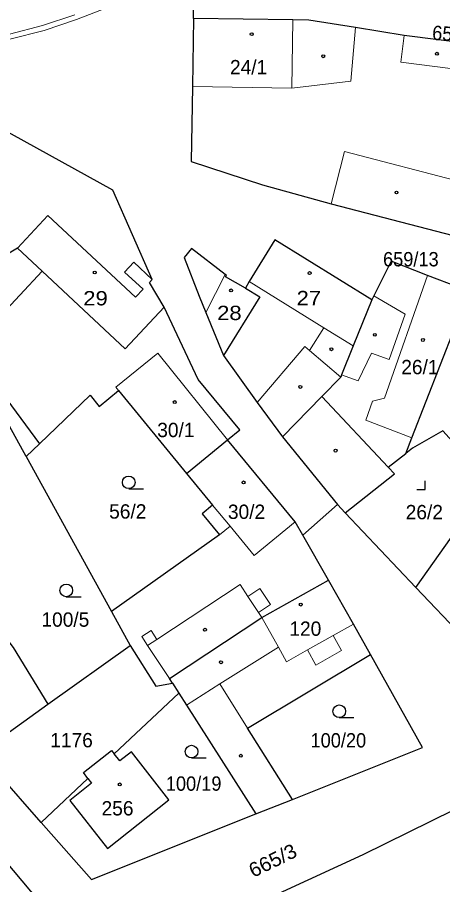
# Model space of a CAD drawing. Extents: x -758887 to -754328, y -1031688 to -1029144.
# Drawn here: x -756312.6 to -756262.1, y -1030550.3 to -1030447.4 of the extents above; entities that cross this region are included whole.
import ezdxf
from ezdxf.enums import TextEntityAlignment as Align

# ---------------------------------------------------------------- set-up
doc = ezdxf.new("R2010")
doc.units = 0
doc.header["$LTSCALE"] = 0.68
for name, color, linetype, lineweight in [('1', 7, 'Continuous', 25), ('13', 7, 'Continuous', 13), ('3', 7, 'Continuous', 25), ('4', 7, 'Continuous', 13), ('5', 7, 'Continuous', 25)]:
    doc.layers.add(name, color=color, linetype=linetype, lineweight=lineweight)
doc.layers.add('2', color=7, linetype='Continuous')

msp = doc.modelspace()

# ---------------------------------------------------------------- linework, layer by layer
at = {"layer": '1'}
for p, q in [((-756291.68, -1030447.55), (-756291.6, -1030443.2)), ((-756292.48, -1030501.5), (-756287.62, -1030497.5)), ((-756281.1, -1030497.15), (-756274.56, -1030505.16)), ((-756265.25, -1030515.03), (-756256.49, -1030502.6)), ((-756278.68, -1030508.83), (-756274.56, -1030505.16)), ((-756275.62, -1030514.13), (-756278.68, -1030508.83)), ((-756265.25, -1030515.03), (-756252.53, -1030528.46)), ((-756308.95, -1030528.87), (-756299.17, -1030521.88)), ((-756293.42, -1030527.54), (-756301.08, -1030534.74)), ((-756317.02, -1030534.63), (-756308.95, -1030528.87)), ((-756309.74, -1030542.89), (-756317.02, -1030534.63)), ((-756304.2, -1030537.67), (-756309.74, -1030542.89)), ((-756284.28, -1030541.87), (-756279.91, -1030540.14))]:
    msp.add_line(p, q, dxfattribs=at)
for points in [[(-756291.68, -1030447.55), (-756291.8, -1030455.61), (-756291.93, -1030464.52)], [(-756252.57, -1030451.52), (-756258.83, -1030450.57), (-756266.65, -1030449.57), (-756272.45, -1030448.6), (-756277.96, -1030447.75), (-756279.88, -1030447.72), (-756291.68, -1030447.55)], [(-756295.16, -1030481.76), (-756296.9, -1030478.86), (-756296.56, -1030478.49), (-756301.26, -1030467.91), (-756316.33, -1030459.62)], [(-756291.93, -1030464.52), (-756283.46, -1030467.28), (-756275.34, -1030469.53), (-756260.84, -1030473.29)], [(-756309.65, -1030477.51), (-756312.58, -1030474.78), (-756314.65, -1030475.99), (-756321.14, -1030471.61)], [(-756270.49, -1030480.92), (-756282.03, -1030473.78), (-756285.04, -1030478.74), (-756285.51, -1030479.51)], [(-756285.51, -1030479.51), (-756287.86, -1030478.19), (-756287.76, -1030478.01), (-756287.92, -1030477.89), (-756291.9, -1030474.82), (-756292.79, -1030475.9), (-756290.99, -1030480.46), (-756290.22, -1030482.42), (-756288.1, -1030487.49)], [(-756263.88, -1030478.04), (-756268.2, -1030476.33), (-756270.25, -1030480.45), (-756270.49, -1030480.92)], [(-756309.65, -1030477.51), (-756314.96, -1030483.22), (-756313.79, -1030484.31), (-756317.3, -1030488.07), (-756309.97, -1030497.97)], [(-756309.65, -1030477.51), (-756299.77, -1030486.71), (-756295.16, -1030481.76)], [(-756258.94, -1030479.89), (-756260.13, -1030479.44), (-756263.88, -1030478.04)], [(-756285.51, -1030479.51), (-756283.81, -1030480.56), (-756288.1, -1030487.49)], [(-756266.46, -1030499.12), (-756265.73, -1030497.26), (-756258.94, -1030479.89)], [(-756270.49, -1030480.92), (-756272.69, -1030486.38), (-756274.08, -1030489.82), (-756274.19, -1030490.09), (-756276.43, -1030492.38), (-756281.1, -1030497.15)], [(-756287.62, -1030497.5), (-756286.17, -1030496.31), (-756291.12, -1030490.34), (-756295.16, -1030481.76)], [(-756288.1, -1030487.49), (-756284.12, -1030493.1), (-756281.1, -1030497.15)], [(-756309.97, -1030497.97), (-756303.94, -1030492.23), (-756302.86, -1030493.54), (-756300.58, -1030491.67), (-756292.48, -1030501.5)], [(-756311.54, -1030499.47), (-756313.51, -1030495.89), (-756330.09, -1030509.29)], [(-756256.49, -1030502.6), (-756262.05, -1030496.44), (-756265.67, -1030498.5), (-756266.46, -1030499.12)], [(-756278.68, -1030508.83), (-756279.61, -1030507.23), (-756287.62, -1030497.5)], [(-756309.97, -1030497.97), (-756311.54, -1030499.47), (-756301.4, -1030517.85)], [(-756273.64, -1030506.17), (-756267.79, -1030501.56), (-756268.54, -1030500.76), (-756266.46, -1030499.12)], [(-756292.48, -1030501.5), (-756289.4, -1030505.25), (-756290.63, -1030506.27), (-756288.57, -1030508.78), (-756301.4, -1030517.85), (-756299.17, -1030521.88)], [(-756274.56, -1030505.16), (-756273.64, -1030506.17), (-756265.25, -1030515.03)], [(-756294.17, -1030526.36), (-756294.52, -1030525.81), (-756283.55, -1030518.59), (-756275.62, -1030514.13)], [(-756270.66, -1030522.96), (-756272.68, -1030519.36), (-756275.62, -1030514.13)], [(-756314.73, -1030516.53), (-756313.61, -1030518.09), (-756315.11, -1030519.53), (-756313.06, -1030522.12), (-756308.95, -1030528.87)], [(-756299.17, -1030521.88), (-756296.14, -1030526.71), (-756294.17, -1030526.36), (-756293.42, -1030527.54)], [(-756279.91, -1030540.14), (-756285.25, -1030531.68), (-756270.66, -1030522.96)], [(-756279.91, -1030540.14), (-756264.47, -1030533.99), (-756270.66, -1030522.96)], [(-756293.42, -1030527.54), (-756292.51, -1030528.97), (-756284.28, -1030541.87)], [(-756304.2, -1030537.67), (-756303.78, -1030538.21), (-756306.36, -1030540.26), (-756301.89, -1030545.97), (-756294.58, -1030540.2), (-756299.01, -1030534.52), (-756300.41, -1030535.56), (-756301.08, -1030534.74)], [(-756304.2, -1030537.67), (-756304.74, -1030536.97), (-756301.39, -1030534.35), (-756301.08, -1030534.74)], [(-756276.81, -1030615.63), (-756276.9, -1030606.22), (-756295.51, -1030569.46), (-756318.87, -1030541.69)], [(-756238.06, -1030581.25), (-756260.8, -1030541.42), (-756271.57, -1030546.71), (-756294.15, -1030557.1), (-756273.96, -1030597.77)], [(-756309.74, -1030542.89), (-756303.79, -1030549.64), (-756284.28, -1030541.87)]]:
    msp.add_lwpolyline(points, dxfattribs=at)
at = {"layer": '13'}
for points in [[(-756317.15, -1030444.76), (-756315.55, -1030449.81), (-756313.48, -1030450), (-756309.41, -1030448.97), (-756305.55, -1030447.66), (-756295.4, -1030443.7)], [(-756305.75, -1030447.1), (-756309.59, -1030448.39), (-756313.52, -1030449.4), (-756315.09, -1030449.25), (-756316.59, -1030444.54)]]:
    msp.add_lwpolyline(points, dxfattribs=at)
at = {"layer": '3'}
for p, q in [((-756299.363, -1030503.3), (-756297.613, -1030503.3)), ((-756306.773, -1030516.12), (-756305.023, -1030516.12)), ((-756274.363, -1030530.44), (-756272.613, -1030530.44)), ((-756291.903, -1030535.23), (-756290.153, -1030535.23))]:
    msp.add_line(p, q, dxfattribs=at)
msp.add_lwpolyline([(-756265.161, -1030503.38), (-756264.16, -1030503.38), (-756264.16, -1030502.38)], dxfattribs=at)
for centre in [(-756299.3629, -1030502.5498), (-756306.7729, -1030515.3698), (-756274.3629, -1030529.6898), (-756291.9029, -1030534.4798)]:
    msp.add_circle(centre, 0.75, dxfattribs=at)
at = {"layer": '4'}
for p, q in [((-756279.88, -1030447.72), (-756280, -1030455.79)), ((-756267.06, -1030452.74), (-756266.65, -1030449.57)), ((-756280, -1030455.79), (-756291.8, -1030455.61)), ((-756273.73, -1030463.33), (-756275.34, -1030469.53)), ((-756259.7, -1030466.97), (-756273.73, -1030463.33)), ((-756308.97, -1030470.9), (-756312.58, -1030474.78)), ((-756298.54, -1030480.61), (-756308.97, -1030470.9)), ((-756298.76, -1030476.44), (-756299.85, -1030477.62)), ((-756296.56, -1030478.49), (-756298.76, -1030476.44)), ((-756299.85, -1030477.62), (-756297.65, -1030479.66)), ((-756287.92, -1030477.89), (-756290.22, -1030482.42)), ((-756285.04, -1030478.74), (-756276.2, -1030484.21)), ((-756269, -1030492.56), (-756263.88, -1030478.04)), ((-756297.65, -1030479.66), (-756298.54, -1030480.61)), ((-756270.25, -1030480.45), (-756266.54, -1030482.62)), ((-756266.54, -1030482.62), (-756268.45, -1030487.99)), ((-756277.88, -1030486.93), (-756276.2, -1030484.21)), ((-756272.69, -1030486.38), (-756276.2, -1030484.21)), ((-756278.45, -1030486.43), (-756284.12, -1030493.1)), ((-756300.9, -1030491.28), (-756300.58, -1030491.67)), ((-756276.43, -1030492.38), (-756268.54, -1030500.76)), ((-756271.2, -1030495.18), (-756270.4, -1030492.92)), ((-756270.4, -1030492.92), (-756269, -1030492.56)), ((-756271.2, -1030495.18), (-756265.73, -1030497.26)), ((-756289.4, -1030505.25), (-756287.33, -1030507.76)), ((-756288.57, -1030508.78), (-756287.33, -1030507.76)), ((-756284.47, -1030511.23), (-756287.33, -1030507.76)), ((-756284.47, -1030511.23), (-756279.61, -1030507.23)), ((-756286.13, -1030514.67), (-756296.02, -1030521.17)), ((-756285.2, -1030516.09), (-756286.13, -1030514.67)), ((-756283.78, -1030515.15), (-756285.2, -1030516.09)), ((-756282.54, -1030517.03), (-756283.78, -1030515.15)), ((-756285.2, -1030516.09), (-756283.96, -1030517.97)), ((-756283.96, -1030517.97), (-756282.54, -1030517.03)), ((-756283.96, -1030517.97), (-756283.55, -1030518.59)), ((-756281.59, -1030522.08), (-756283.55, -1030518.59)), ((-756297.8, -1030520.84), (-756296.71, -1030520.13)), ((-756296.71, -1030520.13), (-756296.02, -1030521.17)), ((-756275.09, -1030520.72), (-756272.68, -1030519.36)), ((-756297.8, -1030520.84), (-756297.11, -1030521.89)), ((-756296.02, -1030521.17), (-756297.11, -1030521.89)), ((-756278.15, -1030522.43), (-756275.09, -1030520.72)), ((-756275.09, -1030520.72), (-756274.09, -1030522.5)), ((-756297.11, -1030521.89), (-756294.52, -1030525.81)), ((-756280.61, -1030523.82), (-756281.59, -1030522.08)), ((-756280.61, -1030523.82), (-756278.15, -1030522.43)), ((-756277.14, -1030524.22), (-756278.15, -1030522.43)), ((-756274.09, -1030522.5), (-756277.14, -1030524.22)), ((-756285.25, -1030531.68), (-756288.53, -1030526.46))]:
    msp.add_line(p, q, dxfattribs=at)
for points in [[(-756272.45, -1030448.6), (-756272.99, -1030454.99), (-756280, -1030455.79)], [(-756267.06, -1030452.74), (-756259.31, -1030453.73), (-756259.97, -1030458.08)], [(-756300.9, -1030491.28), (-756295.91, -1030487.25), (-756287.62, -1030497.5)], [(-756278.45, -1030486.43), (-756277.88, -1030486.93), (-756274.19, -1030490.09)], [(-756274.08, -1030489.82), (-756272.1, -1030490.51), (-756270.52, -1030487.25), (-756268.45, -1030487.99)], [(-756292.51, -1030528.97), (-756288.53, -1030526.46), (-756281.59, -1030522.08)]]:
    msp.add_lwpolyline(points, dxfattribs=at)
at = {"layer": '5'}
for centre in [(-756284.7568, -1030449.4092), (-756276.2668, -1030452.0192), (-756262.7668, -1030451.7292), (-756267.5668, -1030468.1792), (-756303.3868, -1030477.6692), (-756277.8768, -1030477.7392), (-756287.2068, -1030479.7892), (-756270.1368, -1030485.0592), (-756264.4268, -1030485.6692), (-756275.2868, -1030486.7692), (-756278.9868, -1030491.2292), (-756293.8868, -1030493.0392), (-756274.7968, -1030498.7892), (-756285.7268, -1030502.5592), (-756278.9368, -1030517.0492), (-756290.3068, -1030520.0292), (-756288.4068, -1030523.8792), (-756286.0468, -1030534.9692), (-756300.4268, -1030538.3692)]:
    msp.add_circle(centre, 0.175, dxfattribs=at)

# ---------------------------------------------------------------- texts
at = {"layer": '2'}
for s, rotation, width, p in [('659/10', 356, 0.95, (-756260.0788, -1030450.3004)), ('665/3', 26, 1.05, (-756281.8891, -1030548.1522))]:
    msp.add_text(s, height=1.7, rotation=rotation, dxfattribs=dict(at, width=width)).set_placement(p, align=Align.CENTER)
for s, p in [('24/1', (-756285.12, -1030454.17)), ('26/1', (-756264.79, -1030489.73)), ('30/1', (-756293.76, -1030497.19)), ('56/2', (-756299.47, -1030506.85)), ('30/2', (-756285.37, -1030506.89)), ('26/2', (-756264.26, -1030506.93)), ('100/5', (-756306.88, -1030519.67)), ('120', (-756278.389, -1030520.75)), ('1176', (-756306.15, -1030533.97)), ('256', (-756300.689, -1030542.05))]:
    msp.add_text(s, height=1.7, dxfattribs=at).set_placement(p, align=Align.CENTER)
for s, width, p in [('659/13', 0.95, (-756265.859, -1030476.94)), ('29', 1.15, (-756303.3, -1030481.57)), ('27', 1.15, (-756277.97, -1030481.55)), ('28', 1.15, (-756287.41, -1030483.31)), ('100/20', 0.95, (-756274.469, -1030533.99)), ('100/19', 0.95, (-756291.649, -1030539.12))]:
    msp.add_text(s, height=1.7, dxfattribs=dict(at, width=width)).set_placement(p, align=Align.CENTER)

doc.saveas('drawing.dxf')
